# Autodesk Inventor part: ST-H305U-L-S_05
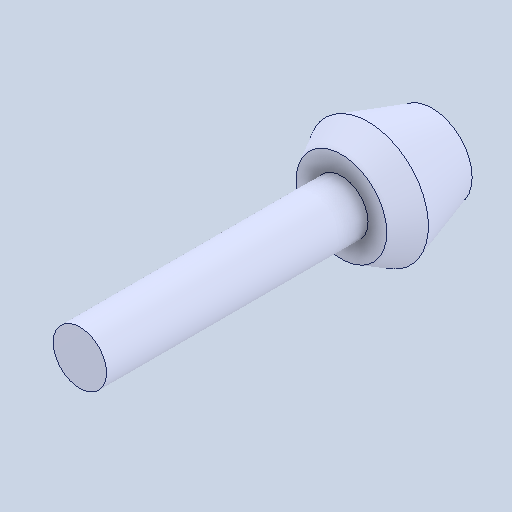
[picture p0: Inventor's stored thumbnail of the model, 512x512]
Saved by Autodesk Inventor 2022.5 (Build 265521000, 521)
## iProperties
Created: 2024-07
Part Number: ST-H305U-L-S_05
Material: 一般
Document SubType Name: Modeling
Designer: ImaoCorp
Density: 1 g/cm^3
Appearance: 既定
Author: ImaoCorp
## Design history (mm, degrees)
feature "ST-H305U-L-S_05"
node "ソリッド1"
